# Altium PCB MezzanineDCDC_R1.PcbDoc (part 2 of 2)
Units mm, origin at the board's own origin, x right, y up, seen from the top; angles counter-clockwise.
Board outline 70 x 70 mm, 4 copper layers (Top Layer, GND 1, Signal, Bottom Layer), stack 1.554 mm thick; 95 components, 53 nets, 436 pads, 382 vias.
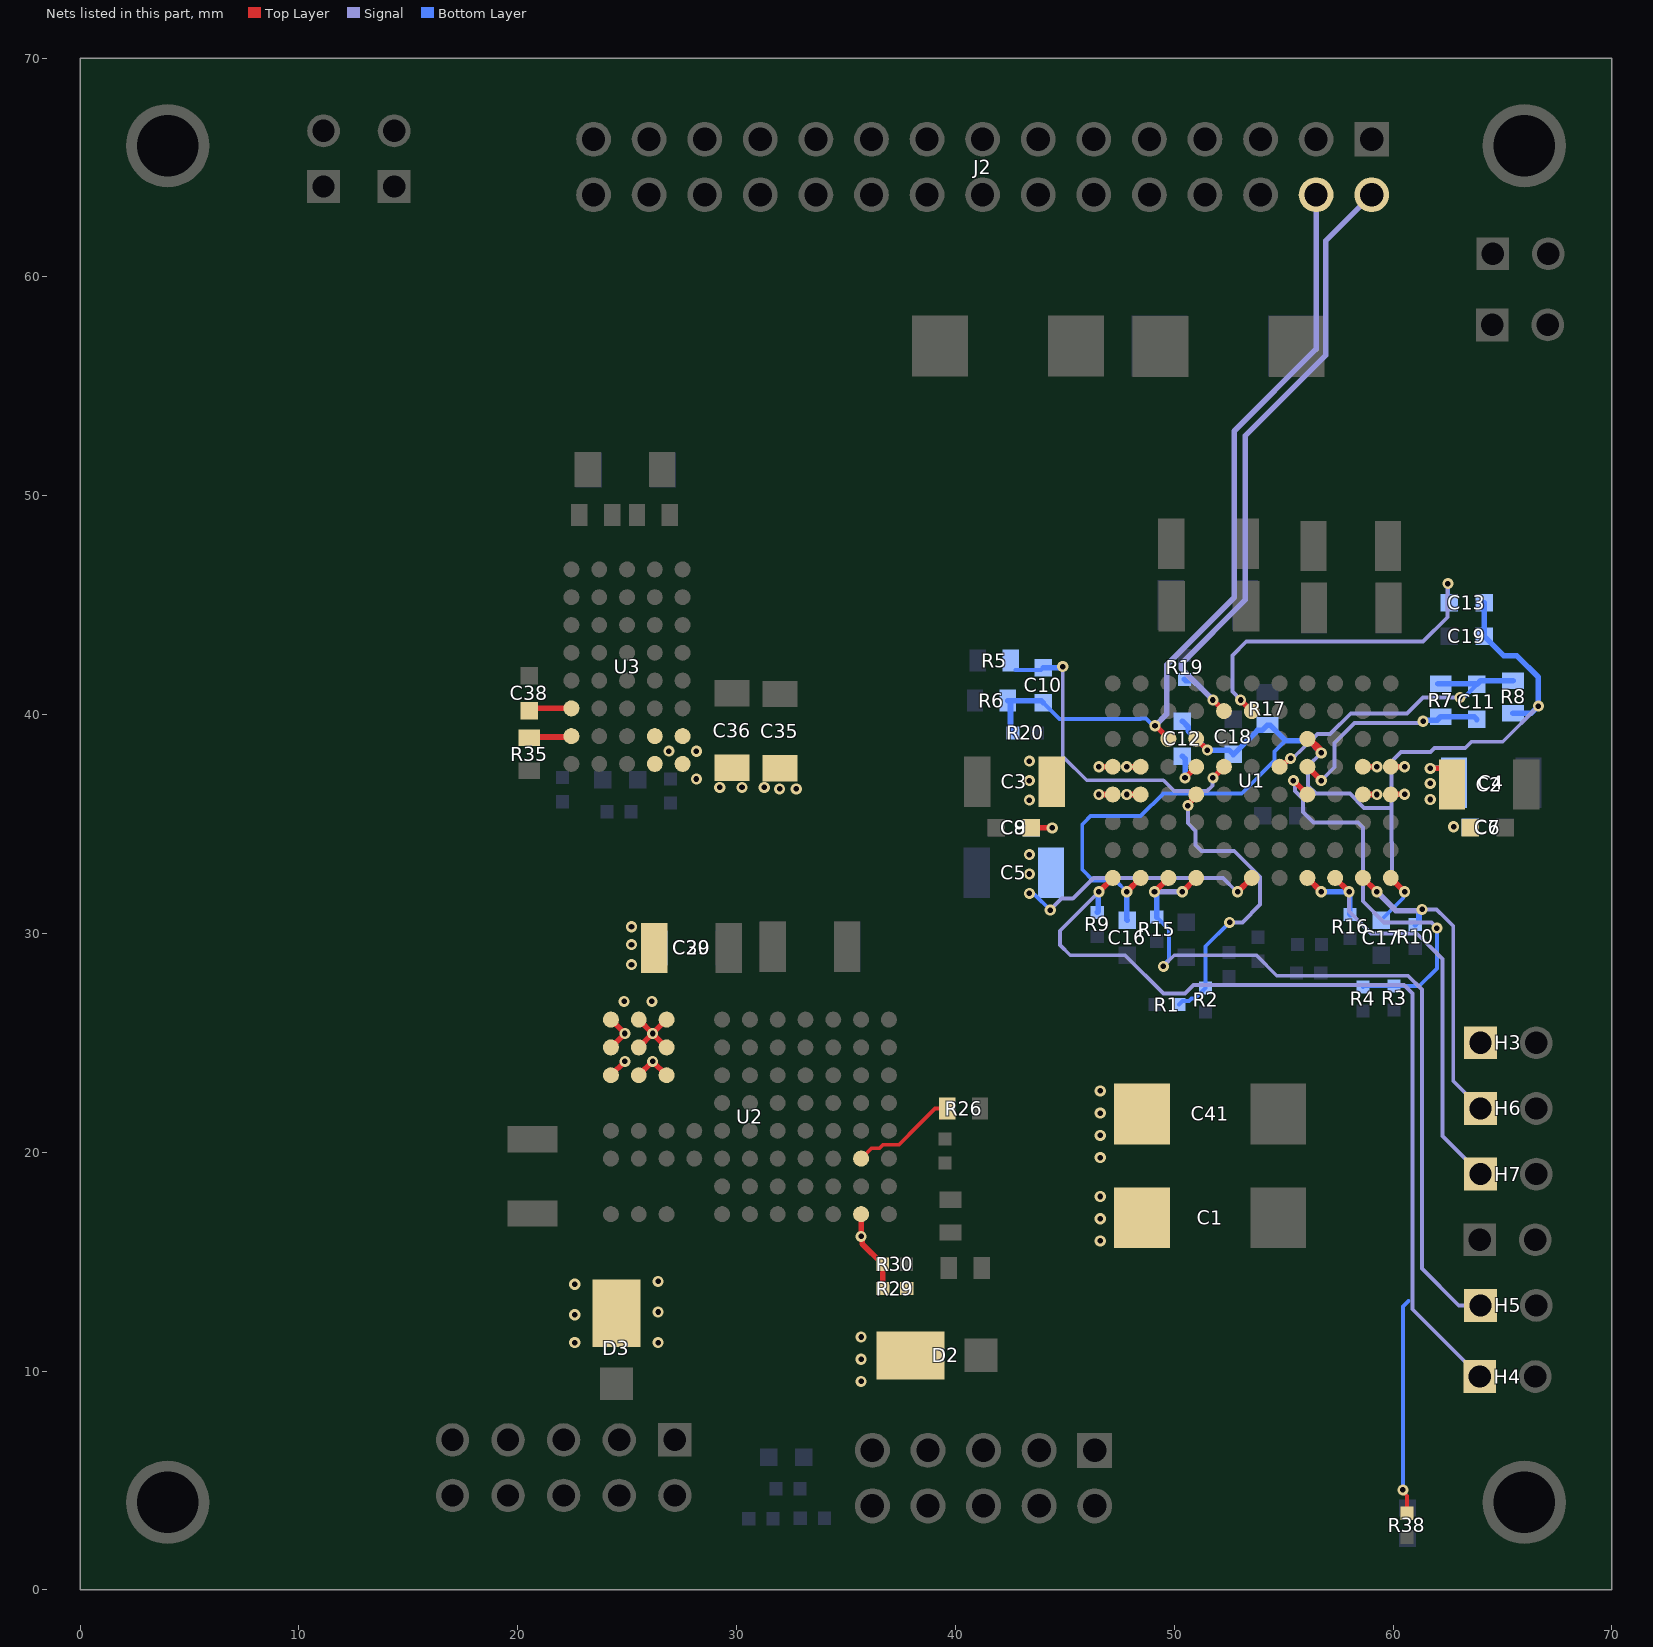
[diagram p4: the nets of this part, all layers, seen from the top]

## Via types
v1: diameter 0.508, hole 0.254, Top Layer to Bottom Layer, tented both sides, 382 vias

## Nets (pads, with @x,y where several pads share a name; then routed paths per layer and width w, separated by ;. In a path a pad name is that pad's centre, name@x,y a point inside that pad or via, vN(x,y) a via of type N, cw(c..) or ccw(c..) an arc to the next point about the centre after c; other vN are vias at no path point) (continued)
RT: R26.2 U2.B6 | length 5.4
  Top Layer w0.178: U2.B6@35.689,19.71 36.159,20.18 36.535,20.18 36.697,20.342 37.415,20.342 37.897,20.824 37.897,20.828 39.065,21.996 R26.2@39.624,21.996 39.624,21.871 R26.2@39.338,21.585
RT_1: R35.2 U3.G1 | length 2
  Top Layer w0.254: R35.2@20.523,38.94 20.561,38.977 22.416,38.977 U3.G1@22.454,39.014
RUN1: R1.1 R2.1 U1.H5 | length 14.1
  Top Layer w0.254: v1(50.622,35.839) U1.H5@51.003,36.347
  Signal w0.178: v1(50.622,35.839) 50.622,35.033 50.968,34.687 50.968,34.032 51.237,33.763 51.384,33.763 51.391,33.769 52.744,33.769 53.924,32.589 53.924,31.318 53.111,30.505 v1(52.527,30.505)
  Bottom Layer w0.178: R1.1@50.216,26.746 50.374,26.904 50.678,26.904 50.795,27.02 50.947,27.02 R2.1@51.435,27.508 51.435,29.413 v1(52.527,30.505)
RUN2: R3.1 R4.1 U1.D5 | length 18.4
  Top Layer w0.254: v1(55.448,36.982) U1.D5@56.083,36.347
  Signal w0.178: v1(55.448,36.982) 55.511,36.919 55.511,36.509 55.891,36.129 55.891,35.549 56.363,35.077 58.395,35.077 58.623,34.849 58.623,31.471 59.594,30.5 61.079,30.5 61.08,30.499 61.751,30.499 v1@62,30.25
  Bottom Layer w0.178: R4.1@58.623,27.559 58.656,27.592 R3.1@60.046,27.592 61.197,27.592 62.002,28.397 v1(62.002,30.242)
S_GND: C12.2 C13.2 C16.2 C17.2 C18.2 C19.2 R8.1 R17.1 U1.A8 U1.D3 U1.H3 U1.K8 | length 58.4
  Top Layer w0.254: v1(47.828,31.902) U1.K8@48.463,32.537 ; U1.H3@51.003,38.887 v1(51.511,38.379) ; v1@56.673,38.427 56.212,38.887 U1.D3@56.083,38.887 v1(56.718,38.252) ; U1.A8@59.893,32.537 v1(60.528,31.902)
  Signal w0.178: v1(56.718,38.252) 56.109,37.643 56.109,36.748 56.471,36.386 58.026,36.386 58.674,35.738 59.931,35.738 ; v1@60.528,31.928 v1(60.528,31.902) 59.944,32.487 59.944,34.156 59.931,34.169 59.931,35.738 ; v1(66.637,40.386) 65.011,38.76 63.576,38.76 63.297,38.481 61.9,38.481 61.709,38.291 60.357,38.291 59.931,37.865 59.931,35.738
  Bottom Layer w0.178: v1(47.828,31.902) 47.307,32.423 46.291,32.423 45.796,32.918 45.796,34.976 45.885,35.065 45.885,35.067 46.175,35.357 48.463,35.357 49.505,36.398 53.086,36.398 54.585,37.897 54.585,38.305 55.091,38.811 ; C17.2@59.461,30.607 60.465,31.61 60.465,31.839 v1(60.528,31.902)
  Bottom Layer w0.254: v1(47.828,31.902) 47.828,30.632 C16.2@47.854,30.607 ; C12.2@50.368,39.7 50.641,39.427 50.641,39.249 v1(51.511,38.379) 52.502,38.379 C18.2@52.705,38.176 53.803,39.274 54.006,39.274 R17.1@54.254,39.522 54.379,39.522 55.091,38.811 56.159,38.811 v1(56.718,38.252) ; C13.2@64.16,45.11 C19.2@64.16,43.586 65.062,42.685 65.657,42.685 66.637,41.705 v1(66.637,40.386) 66.305,40.054 R8.1@65.481,40.054
Sense+_0v9: J2.2 R19.2 U1.G2 | length 29.7
  Top Layer w0.254: v1(51.765,40.665) U1.G2@52.273,40.157
  Signal w0.254: v1(51.765,40.665) 50.321,42.11 50.321,42.321 53.25,45.25 53.25,52.75 56.914,56.414 56.914,61.644 J2.2@59.023,63.752
  Bottom Layer w0.254: R19.2@50.47,41.605 50.521,41.554 50.876,41.554 v1(51.765,40.665)
Sense-_0v9: C10.2 J2.4 R6.1 R20.2 U1.J3 | length 36.8
  Top Layer w0.254: v1@49.276,39.37 49.733,38.913 U1.J3@49.733,38.887
  Signal w0.254: v1(49.121,39.487) 49.657,40.024 49.657,42.268 52.742,45.353 52.742,52.96 56.483,56.701 J2.4@56.483,63.752
  Bottom Layer w0.178: C10.2@44.018,40.538 44.755,39.802 48.468,39.802 48.483,39.817 48.714,39.817 49.043,39.487 v1(49.121,39.487)
  Bottom Layer w0.254: R20.2@42.594,39.218 R20.2@42.617,39.24 ; R20.2@42.639,39.167 42.516,39.289 42.516,40.518 R6.1@42.394,40.64 43.917,40.64 C10.2@44.018,40.538
SS: C38.1 U3.F1 | length 2
  Top Layer w0.254: C38.1@20.523,40.183 20.625,40.284 U3.F1@22.454,40.284
SW1: H5.1 R15.2 U1.H8 U1.J8 | length 35.7
  Top Layer w0.254: v1(49.098,31.902) U1.J8@49.733,32.537 ; v1(50.368,31.902) U1.H8@51.003,32.537
  Signal w0.178: v1@49.5,28.5 50,29 53.75,29 54.683,28.067 60.683,28.067 61.318,27.432 61.318,14.682 63,13 H5.1@64,13
  Signal w0.254: v1(49.098,31.902) v1(50.368,31.902)
  Bottom Layer w0.178: R15.2@49.2,30.742 49.766,30.175 49.766,28.811 49.502,28.547 v1(49.502,28.492)
  Bottom Layer w0.254: v1(49.098,31.902) 49.098,31.834 49.2,31.732 R15.2@49.2,30.742
SW2: H7.1 R16.2 U1.C8 U1.D8 | length 20.7
  Top Layer w0.254: U1.D8@56.083,32.537 v1(56.718,31.902) ; U1.C8@57.353,32.537 v1(57.988,31.902)
  Signal w0.178: v1(57.988,31.902) 57.988,31.012 59,30 61.08,30 62.25,28.83 62.25,20.75 H7.1@64,19
  Bottom Layer w0.254: v1(56.718,31.902) v1(57.988,31.902) 58.014,31.877 58.014,30.886 R16.2@58.039,30.861
SYNC: R29.1 R30.2 U2.B8 | length 3.9
  Top Layer w0.254: U2.B8@35.689,17.17 35.689,16.154 v1@35.714,16.129 ; v1(35.692,16.151) 35.741,16.103 35.741,15.813 R30.2@36.67,14.884 36.674,14.881 36.674,13.771 R29.1@36.678,13.767
  Bottom Layer w0.254: v1@35.692,16.096 v1(35.692,16.151)
TEMP1+: H4.1 R9.1 U1.L8 | length 41.2
  Top Layer w0.254: v1(46.558,31.902) U1.L8@47.193,32.537
  Signal w0.178: v1(46.558,31.902) 44.777,30.121 44.777,29.473 45.25,29 47.75,29 49.5,27.25 50.5,27.25 50.885,27.635 60.504,27.635 60.886,27.253 60.886,12.824 H4.1@63.96,9.75
  Bottom Layer w0.254: R9.1@46.482,30.963 46.52,31.001 46.52,31.864 v1(46.558,31.902)
TEMP2+: H6.1 R10.1 U1.B8 | length 14.7
  Top Layer w0.254: U1.B8@58.623,32.537 v1(59.258,31.902)
  Signal w0.178: v1(61.328,31.096) 61.992,31.096 62.419,30.669 62.75,30.338 62.75,23.25 H6.1@64,22
  Signal w0.254: v1(59.258,31.902) 60.122,31.039 v1@61.316,31.039
  Bottom Layer w0.254: R10.1@61.011,30.404 61.184,30.577 61.184,30.883 61.328,31.027 v1(61.328,31.096)
TRACK1: C12.1 U1.H4 | length 1.8
  Top Layer w0.254: v1(50.491,37.105) U1.H4@51.003,37.617
  Bottom Layer w0.254: C12.1@50.368,38.1 50.495,37.973 50.495,37.109 v1(50.491,37.105)
TRACK2: C13.1 U1.F2 | length 16
  Top Layer w0.254: v1(53.035,40.665) U1.F2@53.543,40.157
  Signal w0.178: v1(53.035,40.665) 52.654,41.046 52.654,42.697 53.289,43.332 61.366,43.332 62.484,44.45 v1@62.484,46.025
  Bottom Layer w0.178: v1(62.501,45.987) 62.501,45.169 C13.1@62.56,45.11
  Bottom Layer w0.254: v1@52.987,40.714 v1(53.035,40.665)
VFB1: C10.1 R5.2 U1.G4 | length 15
  Top Layer w0.254: v1(51.765,37.109) U1.G4@52.273,37.617
  Signal w0.178: v1(44.907,42.189) 44.907,38.093 46,37 49.5,37 50,36.5 51.5,36.5 51.75,36.75 51.75,37.094 v1(51.765,37.109)
  Bottom Layer w0.178: R5.2@42.748,42.037 43.917,42.037 C10.1@44.018,42.138
  Bottom Layer w0.254: C10.1@44.018,42.138 44.856,42.138 v1(44.907,42.189)
VFB2: C11.1 R7.2 R8.2 U1.E4 | length 14.1
  Top Layer w0.254: U1.E4@54.813,37.617 v1(55.321,37.998)
  Signal w0.178: v1(55.321,37.998) 55.411,37.998 55.69,38.278 55.703,38.278 56.541,39.116 57.125,39.116 58.064,40.056 60.636,40.056 61.367,40.787 v1(63.055,40.787)
  Bottom Layer w0.178: v1(63.055,40.787) 63.118,40.85 63.304,40.85 C11.1@63.83,41.376
  Bottom Layer w0.254: R7.2@62.054,41.403 R7.2@62.179,41.403 63.803,41.403 C11.1@63.83,41.376 64.008,41.554 R8.2@65.481,41.554
VIN: C1.1 C2.1 C3.1 C4.1 C5.1 C6.1 C7.1 C8.1 C9.1 C29.1 C30.1 C35.1 C36.1 C41.1 D2.1 D3.1 H3.1 R29.2 R38.1 U1.A4 U1.A5 U1.B4 U1.B5 U1.F8 U1.K4 U1.K5 U1.L4 U1.L5 U2.J1 U2.J2 U2.J3 U2.K1 U2.K2 U2.K3 U2.L1 U2.L2 U2.L3 U3.G4 U3.G5 U3.H4 U3.H5 | length 38.3
  Top Layer w0.178: v1(60.452,4.572) 60.452,4.483 60.63,4.305 R38.1@60.63,3.505
  Top Layer w0.254: U2.L3@24.259,23.52 v1(24.894,24.155) ; U2.L2@24.259,24.79 v1(24.894,25.425) U2.L1@24.259,26.06 ; U2.K3@25.529,23.52 v1(26.164,24.155) U2.J3@26.799,23.52 ; U2.K2@25.529,24.79 v1(26.164,25.425) ; U2.K1@25.529,26.06 v1(26.164,25.425) ; U2.J2@26.799,24.79 v1(26.164,25.425) ; U2.J1@26.799,26.06 v1(26.164,25.425) ; C8.1@43.459,34.823 v1(44.425,34.823) ; v1(46.558,36.347) U1.L5@47.193,36.347 ; v1(46.558,37.617) U1.L4@47.193,37.617 ; v1(47.828,36.347) U1.K5@48.463,36.347 ; v1(47.828,37.617) U1.K4@48.463,37.617 ; v1(52.895,31.902) 52.902,31.902 53.537,32.537 U1.F8@53.543,32.537 ; U1.B5@58.623,36.347 v1(59.258,36.347) ; U1.B4@58.623,37.617 v1(59.258,37.617) ; U1.A5@59.893,36.347 59.9,36.354 60.522,36.354 v1(60.528,36.36) ; U1.A4@59.893,37.617 v1(60.528,37.617) ; v1(61.697,37.541) 62.151,37.541 62.624,37.068 C2.1@62.624,36.982
  Signal w0.178: v1@44.323,31.064 44.856,31.598 45.364,31.598 46.304,32.537 52.222,32.537 52.857,31.902 v1(52.895,31.902)
  Bottom Layer w0.178: v1(43.383,31.826) 43.446,31.763 43.636,31.763 v1(44.334,31.064) ; v1(60.452,4.572) 60.452,12.954 60.706,13.208
  Bottom Layer w0.254: v1(61.697,37.541) 62.519,37.541 62.767,37.293 C4.1@62.767,37.008
  other v1: 35.687,9.525 35.687,10.541 22.606,11.303 26.416,11.303 35.687,11.557 22.606,12.573 26.416,12.7 22.606,13.97 26.416,14.097 46.621,15.946 46.621,16.962 46.621,17.978 46.621,19.756 46.621,20.772 46.621,21.788 46.621,22.804 24.86,26.896 26.13,26.896 25.198,28.575 25.198,29.489 25.198,30.302 43.383,32.715 43.383,33.604 62.763,34.874 43.383,36.093 61.697,36.119 31.964,36.606 32.726,36.606 29.232,36.672 30.248,36.672 31.264,36.672 61.697,36.855 43.383,36.982 28.162,37.056 43.383,37.871 26.907,38.331 28.162,38.326
VOUTS2-: C11.2 R7.1 U1.D4 | length 9.9
  Top Layer w0.254: U1.D4@56.083,37.617 v1(56.718,36.982)
  Signal w0.178: v1(56.718,36.982) 57.328,37.592 57.328,38.709 58.243,39.624 v1@61.371,39.624
  Bottom Layer w0.254: v1(61.371,39.696) 61.42,39.744 62.02,39.744 R7.1@62.179,39.903 63.703,39.903 C11.2@63.83,39.776
pads on no net: J2.1 J2.3 U1.E7 U1.H2 U2.A6
copper on no net: | length 2.7
  Top Layer w0.254: 37.05,19.801 36.959,19.71 37.472,19.71 37.49,19.71 37.592,19.812 v1(37.846,19.812) v1@37.621,19.812 ; v1(50.495,40.665) 51.003,40.157 ; v1(54.305,34.315) 54.813,33.807

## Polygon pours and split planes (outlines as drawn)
0.9V on Top Layer "0.9V_L01_P007" (solid, remove dead copper, pour order 7): 47.625,57.658 47.625,54.356 43.942,50.673 41.91,49.911 41.91,41.148 41.91,40.005 52.07,40.005 52.197,40.005 52.197,57.658
GND on Top Layer "GND_L01_P010" (solid, remove dead copper, pour order 10): 27.713,18.618 27.713,14.378 27.686,14.351 29.464,12.573 42.418,12.573 43.307,13.462 43.307,48.768 47.879,53.34 47.879,67.183 45.466,67.183 44.831,66.548 44.831,61.722 43.815,61.722 42.03,59.937 42.03,52.317 40.005,50.292 40.005,39.37 38.889,38.443 38.889,23.739 38.04,22.555 26.873,22.555 26.797,22.479 26.797,18.669 26.848,18.618
+3.8V on Top Layer "+3.8V_L01_P018" (solid, remove dead copper, pour order 18): 30.988,44.399 33.654,44.399 33.654,34.561 32.285,34.561 32.285,30.937 32.678,30.937 38.889,23.739 38.889,38.443 39.078,38.443 40.029,39.394 40.029,49.269 36.204,53.094 36.204,61.039 37.353,62.188 37.353,62.706 30.988,62.706
-3.8V on Top Layer "-3.8V_L01_P022" (solid, remove dead copper, pour order 22): 25.425,49.936 25.4,49.911 24.257,49.911 24.257,52.578 21.336,52.578 21.336,62.499 24.78,62.499 24.78,67.429 29.718,67.429 29.718,62.738 30.117,62.339 30.117,54.15 30.02,54.15 30.117,53.086 30.117,49.911 28.702,49.911 24.257,49.911
GND on Top Layer "GND_L01_P052" (solid, remove dead copper, pour order 52): 1.27,68.58 68.326,68.58 68.453,68.707 68.453,1.143 1.27,1.143
GND on Top Layer "GND_L01_P017" (solid, remove dead copper, pour order 17): 39.47,62.804 39.813,62.461 39.813,61.882 39.657,61.882 37.209,59.434 37.209,53.213 41.783,53.213 42.442,53.212 42.442,51.976 42.403,51.976 40.441,50.015 40.441,48.681 36.204,53.094 36.204,60.978 38.03,62.804
VIN on Top Layer "VIN_L01_P009" (solid, remove dead copper, pour order 9): 27.586,30.937 27.559,30.964 27.559,33.528 30.099,36.068 32.893,36.068 32.893,39.497 26.162,39.497 25.781,39.116 25.781,36.703 12.065,36.703 11.684,36.163 11.684,29.591 27.559,29.591 27.559,32.004
2.2V on Top Layer "2.2V_L01_P051" (solid, remove dead copper, pour order 51): 57.277,42.545 54.356,42.545 54.356,39.624 65.913,39.624 65.913,42.545 56.832,42.545 56.812,42.565
2.2V on Top Layer "2.2V_L01_P049" (solid, remove dead copper, pour order 49): 57.607,50.317 57.607,53.924 57.658,53.975 57.658,54.61 58.293,54.61 58.293,62.484 65.913,62.484 65.913,40.132 57.693,40.132 57.531,40.294 57.531,50.394
GND on Top Layer "GND_L01_P050" (solid, remove dead copper, pour order 50): 58.547,67.31 58.547,42.214 58.496,42.163 58.496,42.164 52.07,42.164 52.07,67.183 52.197,67.31
GND on Top Layer "GND_L01_P021" (solid, remove dead copper, pour order 21): 30.862,43.895 30.862,62.928 30.122,62.928 30.117,54.15 30.117,43.871 31.623,43.871 31.072,44.021
+3.8V on Top Layer "+3.8V_L01_P019" (solid, remove dead copper, pour order 19): 38.63,24.221 38.63,23.097 37.983,22.45 32.391,22.45 32.285,22.555 32.285,31.531 32.235,31.581 38.649,31.581
GND on Top Layer "GND_L01_P012" (solid, remove dead copper, pour order 12): 27.948,30.504 27.948,33.564 30.191,35.808 32.951,35.808 32.975,35.784 32.987,35.796 33.107,35.796 33.107,40.103 33.095,40.115 32.231,40.115 32.147,40.199 32.303,40.355 32.303,44.399 33.654,44.399 33.654,34.561 31.186,34.561 32.303,34.561 32.303,30.937 31.031,30.852 30.611,30.852 31.031,30.852
0.9V on Top Layer "0.9V_L01_P004" (solid, remove dead copper, pour order 4): 47.625,67.31 47.625,54.399 47.68,54.344 52.578,54.344 52.578,62.484 52.578,67.31
VIN on Top Layer "VIN_L01_P001" (solid, remove dead copper, pour order 1): 51.837,31.115 60.96,31.115 60.979,31.096 61.449,31.096 61.595,31.242 61.544,31.293 61.544,31.826 61.595,31.877 61.595,32.385 64.008,32.385 64.008,27.051 65.151,25.908 65.151,23.749 65.024,23.622 61.849,23.622 61.087,24.384 51.816,24.384 51.816,30.95 51.778,30.988
VIN on Top Layer "VIN_L01_P000" (solid, remove dead copper, pour order 0): 42.545,30.632 42.037,30.124 42.037,22.352 42.418,21.971 52.578,21.971 52.578,30.988 52.451,31.115 42.545,31.115
+3.8V on Bottom Layer "NONET_L-01_P-001" (solid, pour order 26): 31.008,49.116 30.988,49.136 30.988,61.658 32.123,62.794 32.123,67.34 32.078,67.386 37.628,67.386 37.628,49.914 38.166,49.375 39.192,49.375 39.192,48.278 39.037,48.433 30.996,48.433 30.996,49.104
-3.8V on Bottom Layer "-3.8V_L04_P036" (solid, remove dead copper, pour order 36): 24.74,67.427 29.766,67.427 29.711,44.704 24.74,44.704 24.74,54
GND on Bottom Layer "GND_L04_P055" (solid, remove dead copper, pour order 55): 68.58,68.58 68.58,1.143 1.143,1.143 1.27,1.27 1.27,68.58
2.2V on Bottom Layer "2.2V_L04_P029" (solid, remove dead copper, pour order 29): 64.072,46.419 66.802,46.419 66.802,53.721 46.101,53.721 44.933,54.889 44.933,62.575 44.958,62.6 44.958,67.401 40.005,67.401 40.005,62.6 39.497,62.092 39.497,50.165 39.624,50.038 57.277,50.038 57.404,50.165 57.404,46.99 57.975,46.419
+3.8V on Bottom Layer "+3.8V_L04_P033" (solid, remove dead copper, pour order 33): 31.008,49.116 39.188,49.116 39.37,22.225 32.766,22.225 32.766,42.926 30.988,42.926
GND on Bottom Layer "GND_L04_P044" (solid, remove dead copper, pour order 44): 42.672,18.923 39.497,15.748 35.306,15.748 35.055,15.497 33.655,15.497 33.655,21.59 34.036,21.971 39.37,21.971 39.355,21.986 39.355,31.775 42.647,31.775 42.672,31.75
VIN on Bottom Layer "VIN_L04_P043" (solid, remove dead copper, pour order 43): 15.621,34.163 15.621,8.89 33.782,8.89 34.671,8.001 35.052,8.001 35.052,13.081 36.576,14.605 36.576,15.113 36.322,15.367 19.304,15.367 18.288,16.383 18.288,22.987 18.379,23.078 22.581,23.078 22.733,23.23 22.733,34.163
VIN on Bottom Layer "VIN_L04_P042" (solid, remove dead copper, pour order 42): 34.508,12.446 35.814,15.494 39.751,15.494 42.926,18.669 42.926,31.498 45.396,31.498 45.466,31.429 45.466,27.305 49.276,23.495 61.087,23.495 62.992,25.4 62.992,31.242 61.54,32.694 61.54,34.874 63.428,34.874 64.516,33.786 66.294,30.861 66.294,23.114 62.484,23.114 61.468,22.098 61.468,13.081 60.833,12.446
GND on Bottom Layer "GND_L04_P040" (solid, remove dead copper, pour order 40): 31.75,42.672 33.02,42.672 33.02,27.051 31.75,27.051
VIN on Bottom Layer "VIN_L04_P038" (solid, remove dead copper, pour order 38): 22.506,30.977 22.479,31.004 22.479,34.163 27.813,34.163 27.813,39.116 32.004,39.116 32.004,31.369 27.851,31.369 27.459,30.977
GND on Bottom Layer "GND_L04_P037" (solid, pour order 37): 30.988,62.674 30.988,61.658 30.988,42.164 29.591,42.164 29.665,42.238 29.665,62.674
GND on Bottom Layer "GND_L04_P035" (solid, remove dead copper, pour order 35): 42.672,49.276 41.91,50.038 39.56,50.038 39.37,49.847 39.306,49.911 39.116,49.911 39.116,31.568 39.163,31.521 42.672,31.521
0.9V on Bottom Layer "0.9V_L04_P034" (solid, remove dead copper, pour order 34): 45.669,49.276 40.386,49.276 40.386,40.132 40.259,40.005 49.657,40.005 49.657,40.335 49.733,40.411
GND on Bottom Layer "GND_L04_P031" (solid, remove dead copper, pour order 31): 47.371,62.611 47.371,54.991 47.752,54.61 53.404,54.61 53.657,54.864 58.293,54.864 58.293,53.848 45.974,53.848 44.933,54.889 44.933,62.575 44.969,62.611
0.9V on Bottom Layer "0.9V_L04_P030" (solid, remove dead copper, pour order 30): 47.625,54.712 47.727,54.61 52.939,54.61 52.939,67.31 52.578,67.31 47.625,67.31
GND on Bottom Layer "GND_L04_P027" (solid, remove dead copper, pour order 27): 57.15,49.149 57.15,50.165 39.37,50.165 39.37,49.53 52.146,49.53 52.527,49.149
GND on Signal "NONET_L-01_P-001" (solid, remove dead copper, pour order 53): 1.27,68.58 68.58,68.58 68.58,1.143 1.143,1.143 1.27,1.27
GND on GND 1 "NONET_L-01_P-001" (solid, remove dead copper, pour order 54): 1.27,68.58 68.58,68.58 68.58,1.143 1.397,1.143 1.27,1.27

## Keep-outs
Bottom Layer:
  circle w0.254: c4,66 r2.5
  circle w0.254: c4,4 r2.5
  circle w0.254: c66,4 r2.5
  circle w0.254: c66,66 r2.5
Keep-Out Layer:
  lines w0.254: 1.27,1.143 68.58,1.143 68.58,68.58 1.27,68.58 1.27,1.143

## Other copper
Top Layer:
  rectangle net GND: 1.658,1.531 6.985,6.731
  rectangle net GND: 63.119,1.531 68.192,6.858
  rectangle net GND: 62.865,63.373 68.199,68.199
  rectangle net GND: 1.658,63.119 6.858,68.192
  rectangle net 2.2V: 57.071,40.047 60.998,42.565
  rectangle net GND: 64.389,33.807 68.199,39.624
  rectangle net GND: 52.324,42.951 57.26,50.317
  rectangle net 2.2V: 55.956,41.148 59.131,41.808
  rectangle net GND: 19.558,41.046 21.311,42.875
  rectangle net VIN: 21.871,23.002 27.586,30.937
  rectangle net +3.8V: 32.641,23.101 37.744,33.477
  region net GND: 43.063,39.75 46.399,39.742 46.774,39.367 46.774,38.542 43.134,38.542 43.063,38.613
  region net GND: 48.608,39.373 48.608,38.539 46.101,38.539 45.989,38.651 45.989,39.373
  region net GND: 30.122,67.342 32.139,67.342 32.139,62.516 30.122,62.516
  region net GND: 24.003,52.324 21.463,52.324 21.463,50.038 21.59,50.038 24.003,50.038
  region net VIN: 39.497,7.62 35.052,7.62 34.29,8.382 34.163,8.255 26.543,8.255 26.543,11.049 22.733,11.049 22.733,8.382 11.684,8.382 11.684,30.861 22.352,30.861 22.352,23.005 15.494,23.005 15.494,14.986 35.052,14.986 35.052,12.954 39.497,12.954
  region net GND: 57.233,36.371 57.248,36.386 57.248,39.297 57.485,39.535 60.717,39.535 61.076,39.176 61.634,39.185 62.307,39.876 68.167,39.876 68.175,39.448 67.391,38.647 67.296,38.544 62.636,38.544 58.983,38.544 58.5,38.544 58.48,38.525 58.5,38.505 57.97,37.975 57.97,35.914 57.992,35.891 57.992,35.612
  region net 2.2V: 37.209,59.434 40.069,62.293 40.069,67.31 45.024,67.31 45.024,59.563 41.783,59.563 41.783,54.145 41.783,53.213 37.209,53.213
  region net GND: 45.339,67.31 47.356,67.31 47.356,62.484 45.339,62.484
  region net GND: 52.974,67.31 54.991,67.31 54.991,62.484 52.974,62.484
  region net +3.8V: 32.4,67.302 37.353,67.302 37.353,62.476 32.4,62.476
  region net 2.2V: 37.205,59.043 41.711,59.043 41.711,54.217 37.205,54.217
  region net GND: 42.219,59.17 47.172,59.17 47.172,54.344 42.219,54.344
  region net 0.9V: 47.68,59.17 52.633,59.17 52.633,54.344 47.68,54.344
  region net GND: 53.404,59.182 58.356,59.182 58.356,54.356 53.404,54.356
  region net GND: 52.959,24.003 57.912,24.003 57.912,14.351 52.959,14.351
  region net 0.9V: 47.625,67.31 52.578,67.31 52.578,62.484 47.625,62.484
  region net GND: 40.64,16.002 40.64,13.97 41.783,13.97 41.783,16.002
  region net GND: 40.513,23.114 40.513,21.082 41.783,21.082 41.783,23.114
  region net VIN: 45.212,7.747 45.212,12.7 45.085,12.827 54.102,12.827 54.102,7.747
  region net GND: 45.263,7.49 47.549,7.49 47.549,2.283 45.263,2.283
  region net GND: 37.465,7.302 39.751,7.302 39.751,2.095 37.465,2.095
  region net GND: 26.162,8.001 28.448,8.001 28.448,2.794 26.162,2.794
  region net VIN: 39.249,13.71 42.288,13.71 42.294,23.876 52.578,23.876 52.578,12.319 39.243,12.319
  region net VIN: 37.963,12.266 37.338,12.89 37.338,14.224 38.862,14.224 38.862,14.097 39.804,13.155
  region net NetD3_2: 23.241,10.541 25.908,10.541 25.908,2.413 23.241,2.413
  region net NetD2_2: 40.132,12.065 40.132,2.54 44.958,2.54 44.958,12.065
  region net VIN: 61.544,31.826 64.033,31.826 64.008,38.252 64.033,38.227 63.652,38.252 61.544,38.252
  region net GND: 61.29,35.433 61.29,33.223 55.879,33.223 55.353,32.697 55.716,31.533 54.379,31.533 54.379,32.589 53.567,33.401 53.198,33.496 53.061,34.001 52.02,34.85 52.273,35.103 52.427,35.256 54.818,32.866 55.448,33.496 55.448,34.163 53.34,36.271 53.34,36.297 53.619,36.576 54.661,35.535 56.439,35.535 57.252,36.347 57.531,36.347 58.445,35.433
  region net GND: 39.167,35.669 39.167,31.471 42.164,31.471 42.24,31.547 42.24,38.252 41.75,38.252
  region net GND: 42.062,35.669 39.167,35.669 39.167,38.532 42.062,38.532
  region net VIN: 42.545,37.998 45.314,37.998 45.314,30.353 42.545,30.353
  region net VIN: 48.844,36.17 48.387,35.712 43.383,35.712 43.383,38.252 48.26,38.252 48.844,37.668
  region net GND: 46.101,35.408 48.514,35.408 49.098,35.992 49.098,38.011 49.911,37.719 49.911,35.331 52.502,35.331 52.578,35.255 52.578,34.722 52.172,34.722 51.105,33.655 50.927,33.477 50.698,33.147 50.495,32.944 50.267,33.172 49.098,33.172 46.558,33.172 46.38,32.995 45.568,32.995 45.568,35.382 45.593,35.408 45.568,35.433 48.514,35.433
  region net VIN: 58.296,37.722 58.826,38.252 63.068,38.252 63.068,35.712 58.699,35.712 58.296,36.116
  region net 2.2V: 57.607,50.317 61.544,50.317 61.544,42.316 61.544,40.217 57.607,40.217
  region net 0.9V: 49.987,40.157 45.796,40.157 45.796,50.571 51.859,50.571 51.859,42.966 49.987,41.442
  region net VIN: 26.365,39.116 25.971,37.447 25.971,36.83 27.889,36.83 28.626,36.093 32.906,36.093 32.89,38.23 32.89,39.497 31.394,39.497 27.534,39.497 27.153,39.116
  region net GND: 19.775,38.075 21.819,38.075 22.098,38.354 23.444,38.354 23.52,38.278 23.52,37.084 21.539,37.084 21.082,36.627 21.082,36.601 19.609,36.601 19.558,36.652 19.558,37.973 19.674,37.973
  region net GND: 23.47,47.752 21.895,47.752 21.895,41.046 21.92,41.046 22.022,40.945 23.393,40.945
  region net GND: 24.232,47.752 24.232,45.898 25.425,45.898 25.425,44.729 25.756,44.399 33.238,44.399 33.238,40.132 28.296,40.132 27.915,39.751 24.46,39.751 24.232,39.522 24.232,38.379 24.676,38.062 25.502,37.592 25.502,37.084 21.539,37.084 23.165,37.084 23.165,47.752
  region net -3.8V: 25.425,52.959 25.425,49.936 26.441,49.936 26.441,48.235 25.756,48.235 25.756,44.806 25.781,44.78 29.845,44.78 29.845,52.959
  region net GND: 15.875,15.443 15.875,22.555 27.586,22.555 27.586,21.412 27.713,21.285 27.332,20.904 19.712,20.904 19.712,18.999 19.331,18.618 18.95,18.618 18.95,15.443
  region net GND: 19.331,21.539 29.999,21.539 29.999,24.181 29.72,24.46 27.94,24.46 27.94,30.937 32.285,30.937 32.285,22.555 38.132,22.555 37.726,21.151 36.357,20.622 34.444,20.523 34.444,17.094 35.079,16.459 35.079,15.824 30.126,15.824 30.126,17.475 29.745,17.856 27.84,17.856 27.713,17.983 27.713,18.618 19.331,18.618
  region net FIN: 27.434,15.276 19.356,15.276 19.356,18.161 27.434,18.161
Bottom Layer:
  rectangle net GND: 37.728,1.524 39.624,7.239
  rectangle net GND: 45.339,1.778 48.006,7.493
  rectangle net GND: 26.289,2.286 28.956,8.001
  rectangle net NetD3_2: 23.241,2.413 25.908,8.128
  rectangle net GND: 52.273,42.951 57.15,49.403
  region net GND: 46.228,34.925 46.228,33.02 46.482,32.766 51.054,32.766 51.054,33.782 52.197,33.782 52.197,32.893 53.721,32.893 53.721,31.623 56.134,31.623 56.134,32.512 61.214,32.512 61.214,35.433 58.547,35.433 57.785,36.195 54.991,36.195 54.991,33.782 53.721,33.782 53.292,34.925
  region net GND: 24.257,21.336 24.257,18.542 29.083,18.542 29.083,17.145 30.226,17.145 30.226,16.256 30.988,15.494 35.052,15.494 35.052,17.907 35.052,16.891 34.925,16.891 35.052,17.018 34.544,17.526 34.434,20.16 37.892,21.971 32.512,21.971 32.512,26.67 31.75,25.908 29.464,25.908 29.464,21.336
  region net VIN: 28.321,37.973 31.75,37.973 31.75,35.433 28.321,35.433
  region net GND: 19.431,67.501 24.384,67.501 24.384,44.45 30.749,44.45 30.749,42.672 32.004,42.672 32.004,39.116 25.527,39.116 25.273,39.37 19.431,39.37
  region net -3.8V: 25.908,48.26 29.464,48.26 29.464,44.831 25.908,44.831
  region net -3.8V: 25.654,53.213 28.702,53.213 28.702,48.387 25.781,48.387 25.654,48.514
  region net GND: 28.067,30.932 32.512,30.932 32.512,23.749 28.067,23.749
  region net 2.2V: 57.404,40.259 57.404,50.165 61.849,50.165 61.849,42.672 61.214,42.037 61.214,40.259
  region net 0.9V: 47.727,59.019 52.68,59.019 52.68,54.61 47.727,54.61
  region net NetD2_2: 40.107,12.156 45.06,12.156 45.06,7.33 40.107,7.33
  region net +3.8V: 32.766,32.349 37.567,32.349 37.567,27.523 32.766,27.523
  region net +3.8V: 32.766,27.65 37.567,27.65 37.567,22.824 32.766,22.824
  region net VIN: 22.581,27.904 27.455,27.904 27.455,23.078 22.581,23.078
  region net VIN: 22.506,30.977 27.459,30.977 27.459,26.151 22.506,26.151
  region net FIN: 19.355,18.161 27.432,18.161 27.432,15.621 19.355,15.621
  region net GND: 18.783,22.134 22.619,22.134 22.619,19.431 18.783,19.431
  region net VIN: 22.162,14.478 27.114,14.478 27.114,11.013 22.162,11.013
  region net VIN: 34.671,12.827 39.624,12.827 39.624,8.001 34.671,8.001
  region net NetD2_2: 40.107,7.62 45.06,7.62 45.06,2.54 40.107,2.54
  region net 0.9V: 47.625,67.31 52.578,67.31 52.578,62.484 47.625,62.484
  region net GND: 68.021,34.262 64.588,34.262 64.588,39.014 68.021,39.014
  region net 0.9V: 45.669,40.411 49.733,40.411 49.733,42.316 52.019,42.951 52.019,49.279 45.669,49.279
  region net GND: 42.672,31.521 39.163,31.521 39.163,38.227 42.672,38.227
  region net VIN: 45.396,30.567 43.18,30.567 43.18,38.202 45.396,38.202
  region net VIN: 48.844,36.322 48.235,35.712 44.018,35.712 44.018,38.252 48.285,38.252 48.844,37.694
  region net VIN: 64.038,33.782 61.54,33.782 61.54,38.227 64.038,38.227
  region net VIN: 58.242,37.742 58.752,38.252 63.068,38.252 63.068,35.712 58.699,35.712 58.242,36.17

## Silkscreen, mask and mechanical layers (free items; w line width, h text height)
Top Overlay:
  drawing of 18 lines, arcs and shapes, not listed
  text "GND" at 22.606,68.072 h1.02
  text "-3.8V" at 25.146,68.072 h1.02
  text "-3.8V" at 27.686,68.072 h1.02
  text "GND" at 30.226,68.072 h1.02
  text "3.8V" at 33.02,68.072 h1.02
  text "3.8V" at 35.306,68.072 h1.02
  text "GND" at 37.846,68.072 h1.02
  text "2.2V" at 40.386,68.072 h1.02
  text "2.2V" at 42.926,68.072 h1.02
  text "GND" at 45.466,68.072 h1.02
  text "0.9V" at 48.006,68.072 h1.02
  text "0.9V" at 50.546,68.072 h1.02
  text "GND" at 53.34,68.072 h1.02
  text "GND" at 55.88,68.072 h1.02
  text "GND" at 10.16,67.829 h1.02
  text "GND" at 13.462,67.829 h1.02
  text "29" at 19.506,66.228 h1.02
  text "1" at 61.417,66.218 h1.02
  text "Output" at 17.018,64.996 h1.27
  text "30" at 19.558,63.511 h1.02
  text "2" at 61.468,63.5 h1.02
  text "GND" at 3.048,62.992 h1.02
  text "GND" at 65.278,63.003 h1.02
  text "-3.8V" at 9.906,62.23 h1.02
  text "+3.8V" at 13.208,62.23 h1.02
  text "GND" at 23.125,61.976 h1.02 r270
  text "-3.8V" at 25.665,61.976 h1.02 r270
  text "-3.8V" at 28.205,61.976 h1.02 r270
  text "GND" at 30.745,61.976 h1.02 r270
  text "3.8V" at 33.285,61.976 h1.02 r270
  text "3.8V" at 35.825,61.976 h1.02 r270
  text "GND" at 38.365,61.976 h1.02 r270
  text "2.2V" at 41.148,61.977 h1.02 r270
  text "2.2V" at 43.434,61.977 h1.02 r270
  text "GND" at 45.985,61.976 h1.02 r270
  text "0.9V" at 48.525,61.976 h1.02 r270
  text "0.9V" at 51.065,61.976 h1.02 r270
  text "GND" at 53.605,61.976 h1.02 r270
  text "0.9V S-" at 56.388,61.976 h1.02 r270
  text "0.9V S+" at 58.685,61.976 h1.02 r270
  text "2.2V" at 63.246,60.198 h1.02 r90
  text "GND" at 68.823,60.198 h1.02 r90
  text "0.9V" at 63.246,56.896 h1.02 r90
  text "GND" at 68.823,56.896 h1.02 r90
  text "Mounting Holes are connected GND" at 3.048,46.736 h1.02 r90
  text "8045 (-3.8V)" at 14.224,46.736 h1.02
  text "4646 (0.9V. 2.2V)" at 51.308,28.702 h1.02
  text "L1" at 21.49,25.857 h1.02
  text "8033 (+3.8V)" at 39.37,25.654 h1.02
  text "VIN" at 61.468,24.638 h1.02
  text "GND" at 68.315,23.876 h1.02 r90
  text "Temp 2.2V" at 58.42,21.844 h1.02
  text "GND" at 68.315,21.082 h1.02 r90
  text "SW 2.2V" at 59.182,18.796 h1.02
  text "GND" at 68.315,18.034 h1.02 r90
  text "ClockOUT" at 58.674,15.748 h1.02
  text "GND" at 68.315,14.986 h1.02 r90
  text "G8" at 28.856,14.692 h1.02
  text "SW 0.9V" at 59.182,12.7 h1.02
  text "GND" at 68.315,11.938 h1.02 r90
  text "3/21 B#1006" at 3.923,9.779 h1.27 r90
  text "Mezzanine DCDC PCB R1" at 2.527,9.652 h1.27 r90
  text "Temp 0.9V" at 58.42,9.398 h1.02
  text "GND" at 45.466,8.901 h1.02
  text "GND" at 68.315,8.636 h1.02 r90
  text "2.2VPG" at 17.261,8.127 h1.02 r90
  text "3.8PG" at 19.801,8.128 h1.02 r90
  text "0.9V-EN" at 22.098,8.128 h1.02 r90
  text "0.9V-EN" at 34.036,8.139 h1.02
  text "GND" at 37.846,8.139 h1.02
  text "VIN" at 40.641,8.128 h1.02
  text "VIN" at 42.927,8.128 h1.02
  text "GND" at 26.257,8.11 h1.02
  text "VIN" at 23.902,7.823 h1.02
  text "5" at 14.986,6.615 h1.02
  text "1" at 28.702,6.604 h1.02
  text "9" at 33.528,6.107 h1.02
  text "1" at 49.53,6.096 h1.02
  text "Spare Input" at 9.906,5.588 h1.02
  text "10" at 14.986,3.821 h1.02
  text "6" at 28.702,3.821 h1.02
  text "GND" at 21.855,3.302 h1.02 r270
  text "10" at 33.147,3.313 h1.02
  text "2" at 49.529,3.302 h1.02
  text "0.9VPG" at 14.732,2.297 h1.02
  text "GND" at 26.416,2.297 h1.02
  text "VIN" at 23.862,2.266 h1.02
  text "M-EN" at 18.503,2.209 h1.02
  text "M-EN" at 34.798,1.524 h1.02
  text "GND" at 37.846,1.535 h1.02
  text "VIN" at 40.641,1.524 h1.02
  text "VIN" at 43.181,1.524 h1.02
  text "GND" at 45.466,1.535 h1.02
  text "GND" at 2.794,1.27 h1.02
  text "GND" at 65.278,1.27 h1.02
Bottom Overlay:
  drawing of 10 lines, arcs and shapes, not listed
  text "GND" at 11.938,68.337 h1.02
  text "GND" at 15.24,68.337 h1.02
  text "GND" at 24.13,67.575 h1.02
  text "-3.8V" at 26.924,67.575 h1.02
  text "-3.8V" at 29.464,67.575 h1.02
  text "GND" at 32.004,67.575 h1.02
  text "3.8V" at 34.544,67.575 h1.02
  text "3.8V" at 37.084,67.575 h1.02
  text "GND" at 39.624,67.575 h1.02
  text "2.2V" at 42.165,67.564 h1.02
  text "2.2V" at 44.451,67.564 h1.02
  text "GND" at 47.244,67.575 h1.02
  text "0.9V" at 49.784,67.575 h1.02
  text "0.9V" at 52.07,67.575 h1.02
  text "GND" at 54.864,67.575 h1.02
  text "29" at 21.591,66.051 h1.02
  text "1" at 60.96,66.04 h1.02
  text "Output" at 19.812,64.742 h1.27
  text "30" at 21.59,63.511 h1.02
  text "2" at 61.215,63.246 h1.02
  text "GND" at 5.08,63.003 h1.02
  text "GND" at 67.31,63.003 h1.02
  text "-3.8V" at 11.673,62.484 h1.02 r90
  text "+3.8V" at 14.721,62.484 h1.02 r90
  text "GND" at 69.331,62.23 h1.02 r90
  text "GND" at 23.611,61.976 h1.02 r90
  text "-3.8V" at 26.151,61.976 h1.02 r90
  text "-3.8V" at 28.691,61.976 h1.02 r90
  text "GND" at 31.485,61.976 h1.02 r90
  text "0.9V S-" at 56.885,61.976 h1.02 r90
  text "0.9V S+" at 59.425,61.976 h1.02 r90
  text "3.8V" at 34.025,61.722 h1.02 r90
  text "3.8V" at 36.565,61.722 h1.02 r90
  text "GND" at 39.105,61.722 h1.02 r90
  text "2.2V" at 41.402,61.723 h1.02 r90
  text "2.2V" at 44.196,61.723 h1.02 r90
  text "GND" at 46.725,61.722 h1.02 r90
  text "0.9V" at 49.265,61.722 h1.02 r90
  text "0.9V" at 51.805,61.722 h1.02 r90
  text "GND" at 54.345,61.722 h1.02 r90
  text "2.2V" at 62.738,61.214 h1.02 r90
  text "No remote sense, R19, R20 = 0 ohm jumper" at 5.512,61.156 h1.02 r90
  text "Use remote sense, R19, R20 = open" at 4.409,61.117 h1.02 r90
  text "Mounting Holes are connected GND" at 3.048,60.96 h1.02 r90
  text "GND" at 69.331,58.928 h1.02 r90
  text "0.9V" at 62.738,57.912 h1.02 r90
  text "8045 (-3.8V)" at 25.908,46.99 h1.02
  text "4646 (0.9V. 2.2V)" at 47.498,44.704 h1.02
  text "VIN" at 62.249,24.5 h1.02
  text "GND" at 68.261,23.75 h1.02 r270
  text "Mezzanine DCDC PCB R1" at 2.654,22.733 h1.27 r90
  text "2.2V" at 62.251,22 h1.02
  text "T2" at 62.25,21 h1.02
  text "GND" at 68.261,21 h1.02 r270
  text "2.2V" at 62.251,18.75 h1.02
  text "GND" at 68.261,18 h1.02 r270
  text "SW" at 62.25,17.761 h1.02
  text "3/21 B#1006" at 3.923,16.002 h1.27 r90
  text "CLK" at 62.21,15.761 h1.02
  text "GND" at 68.221,15 h1.02 r270
  text "8033 (+3.8V)" at 34.29,14.732 h1.02
  text "0.9V" at 62.25,13.011 h1.02
  text "SW" at 62.25,12.011 h1.02
  text "GND" at 68.261,12 h1.02 r270
  text "0.9V" at 62.21,9.511 h1.02
  text "GND" at 68.221,8.75 h1.02 r270
  text "T1" at 62.23,8.382 h1.02
  text "GND" at 47.327,7.65 h1.02
  text "0.9V-EN" at 37.338,7.631 h1.02
  text "GND" at 39.624,7.631 h1.02
  text "VIN" at 41.909,7.62 h1.02
  text "VIN" at 44.549,7.572 h1.02
  text "9" at 34.95,6.132 h1.02
  text "1" at 48.26,6.096 h1.02
  text "Power On" at 62.433,5.55 h1.27
  text "10" at 35.23,4.303 h1.02
  text "2" at 48.261,3.556 h1.02
  text "GND" at 47.581,1.808 h1.02
  text "M-EN" at 37.084,1.778 h1.02
  text "GND" at 39.878,1.789 h1.02
  text "VIN" at 44.449,1.778 h1.02
  text "VIN" at 42.009,1.73 h1.02
  text "GND" at 4.826,1.281 h1.02
  text "GND" at 67.31,1.281 h1.02
Mechanical 1:
  the board outline again, w0.254
Top Assembly:
  drawing of 57 lines, arcs and shapes, not listed
  text "REVISION HISTORY" at 75.235,172.161 h1.52
  text "ECO" at 56.185,168.986 h1.27
  text "REV" at 61.9,168.986 h1.27
  text "DESCRIPTION" at 73.33,168.986 h1.27
  text "ENG" at 94.285,168.986 h1.27
  text "DATE" at 109.525,168.986 h1.27
  text "-" at 57.455,165.176 h1.27
  text "1" at 63.195,165.125 h1.27
  text "PROTOTYPE" at 70.815,165.125 h1.27
  text "J. JUNEAU" at 94.31,165.125 h1.27
  text "03-12-2021" at 106.426,165.1 h1.27
  text "NOTES: UNLESS OTHERWISE SPECIFIED" at 38.608,147.066 h2.03
  text "1. WORKMANSHIP SHALL BE IN ACCORDANCE WITH IPC-A-610." at 38.989,143.205 h1.27
  text "MAXIMUM SOLDER TEMPERATURE IS 240 DEGREES CELSIUS." at 41.529,136.855 h1.27
  text "3. PARTS TO OMIT WILL BE SPECIFIED ON THE BILL OF MATERIALS." at 37.973,133.045 h1.27
  text "LOCATIONS OF OMITTED PARTS SHALL BE FREE OF SOLDER." at 41.148,130.505 h1.27
  text "MASK THE SOLDER STENCIL WHERE SMT PARTS ARE OMITTED." at 41.148,127.965 h1.27
  text "TITLE:" at 31.039,92.953 h1.27
  text "ASSEMBLY DRAWING" at 38.659,92.953 h1.27
  text "REV" at 84.836,92.71 h1.27
  text "Board Number:" at 64.77,91.186 h1.27
  text "1006" at 78.486,91.186 h1.27
  text "1" at 86.106,89.827 h1.65
  text "SUPER-FGD MEZZANINE DCDC PCB" at 31.315,89.789 h1.27
  text "MezzanineDCDC_R1.PCB" at 73.33,83.464 h1.27
  text "FILENAME:" at 58.979,83.337 h1.27
  text "SHT 1 OF 1" at 104.191,83.337 h1.27
Drill Drawing:
  drawing of 159 lines, arcs and shapes, not listed
  text "REVISION HISTORY" at 154.407,148.184 h1.52
  text "ECO" at 135.357,145.009 h1.27
  text "REV" at 141.072,145.009 h1.27
  text "DESCRIPTION" at 152.502,145.009 h1.27
  text "ENG" at 173.457,145.009 h1.27
  text "DATE" at 188.697,145.009 h1.27
  text "-" at 136.627,141.199 h1.27
  text "1" at 142.367,141.148 h1.27
  text "PROTOTYPE" at 149.987,141.148 h1.27
  text "J. JUNEAU" at 173.482,141.148 h1.27
  text "03-12-2021" at 185.598,141.122 h1.27
  text "LAYER STRUCTURE" at 136.703,130.962 h2.16
  text "L1 - TOP SIDE" at 160.568,125.54 h1.27
  text "L2 - GND" at 160.568,121.222 h1.27
  text "L3 - SIGNALS" at 160.568,116.65 h1.27
  text "L4 - BOTTOM SIDE" at 160.568,112.078 h1.27
  text "NOTES: UNLESS OTHERWISE SPECIFIED" at 112.293,84.811 h2.16
  text "1. FAB PER IPC-A-600." at 112.928,79.096 h1.27
  text "2. MATERIAL: -LEAD FREE ASSEMBLY COMPLIANT, FR-4" at 112.293,75.286 h1.27
  text "OR EQUIVALENT." at 129.311,72.746 h1.27
  text "-FINISHED THICKNESS TO BE 0.062 +/- 10%" at 127.406,69.571 h1.27
  text "-TOTAL OF 4 LAYERS WITH 2 OZ. CU ON ALL LAYERS" at 127.406,66.396 h1.27
  text "3. SIZE: CUT TO DIMENSIONS AND TOLERANCES SHOWN." at 112.166,59.411 h1.27
  text "4. FINISH: -SMOBC USING LPI BOTH SIDES, COLOR GREEN." at 112.166,53.95 h1.27
  text "-GOLD IMMERSION BOTH SIDES." at 123.596,50.775 h1.27
  text "-FOR SILKSCREENS: USE WHITE NON-CONDUCTIVE INK." at 123.596,47.6 h1.27
  text "5. PCBS ARE TO BE RoHS COMPLIANT." at 112.141,41.529 h1.27
  text "6. ALL VIAS ARE FILLED, PLATED AND TENTED." at 112.359,36.99 h1.27
  text "7. ENIG" at 112.014,32.893 h1.27
  text "8. 2 OZ COPPER ON ALL LAYERS" at 112.09,29.261 h1.27
  text "Symbol" at 217.853,24.807 h1.83
  text "Count" at 230.702,24.807 h1.83
  text "Hole Size" at 245.938,24.807 h1.83
  text "Plated" at 274.885,24.807 h1.83
  text "Hole Type" at 287.735,24.807 h1.83
  text "Drill Layer Pair" at 306.373,24.807 h1.83
  text "Via/Pad" at 344.462,24.807 h1.83
  text "Pad Shape" at 359.444,24.807 h1.83
  text "Template" at 378.387,24.807 h1.83
  text "Description" at 413.429,24.807 h1.83
  text "Hole Tolerance (+)" at 435.114,24.807 h1.83
  text "Hole Tolerance (-)" at 468.988,24.807 h1.83
  text "4" at 230.702,20.997 h1.52
  text "110.24mil (2.800mm)" at 245.938,20.997 h1.52
  text "PTH" at 274.885,20.997 h1.52
  text "Round" at 287.735,20.997 h1.52
  text "Top Layer - Bottom Layer" at 306.373,20.997 h1.52
  text "Pad" at 344.462,20.997 h1.52
  text "Rounded" at 359.444,20.997 h1.52
  text "c381h280_2670034071" at 378.387,20.997 h1.52
  text "10" at 230.702,17.187 h1.52
  text "42.00mil (1.067mm)" at 245.938,17.187 h1.52
  text "PTH" at 274.885,17.187 h1.52
  text "Round" at 287.735,17.187 h1.52
  text "Top Layer - Bottom Layer" at 306.373,17.187 h1.52
  text "Pad" at 344.462,17.187 h1.52
  text "(Mixed)" at 359.444,17.187 h1.52
  text "(Mixed)" at 378.387,17.187 h1.52
  text "30" at 230.702,13.377 h1.52
  text "40.00mil (1.016mm)" at 245.938,13.377 h1.52
  text "PTH" at 274.885,13.377 h1.52
  text "Round" at 287.735,13.377 h1.52
  text "Top Layer - Bottom Layer" at 306.373,13.377 h1.52
  text "Pad" at 344.462,13.377 h1.52
  text "(Mixed)" at 359.444,13.377 h1.52
  text "(Mixed)" at 378.387,13.377 h1.52
  text "TITLE:" at 109.703,12.334 h1.27
  text "FABRICATION DRAWING" at 117.323,12.334 h1.27
  text "REV" at 163.5,12.09 h1.27
  text "Board Number:" at 143.434,10.566 h1.27
  text "1006" at 157.15,10.566 h1.27
  text "30" at 230.702,9.567 h1.52
  text "41.73mil (1.060mm)" at 245.938,9.567 h1.52
  text "PTH" at 274.885,9.567 h1.52
  text "Round" at 287.735,9.567 h1.52
  text "Top Layer - Bottom Layer" at 306.373,9.567 h1.52
  text "Pad" at 344.462,9.567 h1.52
  text "(Mixed)" at 359.444,9.567 h1.52
  text "(Mixed)" at 378.387,9.567 h1.52
  text "1" at 164.77,9.207 h1.65
  text "SUPER-FGD MEZZANINE DCDC PCB" at 109.979,9.169 h1.27
  text "382" at 230.702,5.757 h1.52
  text "10.00mil (0.254mm)" at 245.938,5.757 h1.52
  text "PTH" at 274.885,5.757 h1.52
  text "Round" at 287.735,5.757 h1.52
  text "Top Layer - Bottom Layer" at 306.373,5.757 h1.52
  text "Via" at 344.462,5.757 h1.52
  text "Rounded" at 359.444,5.757 h1.52
  text "v51h25m0mx0_2670034071" at 378.387,5.757 h1.52
  text "MezzanineDCDC_R1.PCB" at 151.994,2.845 h1.27
  text "FILENAME:" at 137.643,2.718 h1.27
  text "SHT 1 OF 1" at 182.855,2.718 h1.27
  text "456 Total" at 230.702,1.947 h1.52

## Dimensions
70,70 to 70,0 on Drill Drawing
0,70 to 70,70 on Drill Drawing
0,0 to 0,70 on Mechanical 15
0,70 to 70,70 on Mechanical 15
